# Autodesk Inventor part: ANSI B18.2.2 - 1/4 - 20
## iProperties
Comments: To add or edit properties for Autodesk Inventor files, use iProperties.
Created: 2005-06
Part Number: ANSI B18.2.2 - 1/4 - 20
Vendor: Autodesk Inc.
Document SubType Name: Modeling
Designer: John Blackburn
Material: Default
Description: Hex Nut
Standard: ANSI B18.2.2
Size Designation: 1/4 - 20
Alert: To add or edit properties for Autodesk Inventor files, use iProperties.
Control State: 0
Master: False
Checked Out: False
Shininess: 64.0
Length Units: 11272
Angle Units: 11279
Time Units: 11290
Mass Units: 11286
Length Display Precision: 3
Angle Display Precision: 2
Compacted: True
EGR: 3
Classification: un/spsc 31161727
Density: 0.0
Volumn: 0.0
Area: 0.0
PropertySet Name: Model Information
Author: John Blackburn
Revision Number: 8
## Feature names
1. Body [Extrusion]
2. Chamfer1 [Revolution]
3. Thread [Hole]
4. Chamfer2
5. Chamfer3
